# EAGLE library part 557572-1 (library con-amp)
AMP connector
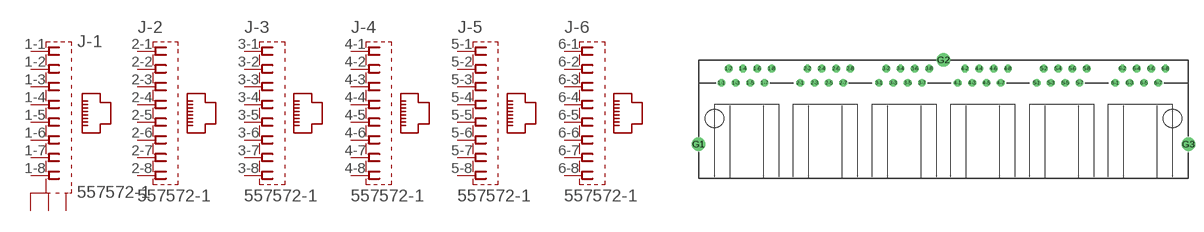
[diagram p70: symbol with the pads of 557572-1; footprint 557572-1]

Designator prefix J; gates -1=JACK8SH3 -2=JACK8_SH -3=JACK8_SH -4=JACK8_SH -5=JACK8_SH -6=JACK8_SH

## 557572-1 (MPN: 5557572-1; OC_FARNELL: unknown; OC_NEWARK: 14N8801)  [557572-1]
1-1  -1:1  pas
1-2  -1:2  pas
1-3  -1:3  pas
1-4  -1:4  pas
1-5  -1:5  pas
1-6  -1:6  pas
1-7  -1:7  pas
1-8  -1:8  pas
2-1  -2:1  pas
2-2  -2:2  pas
2-3  -2:3  pas
2-4  -2:4  pas
2-5  -2:5  pas
2-6  -2:6  pas
2-7  -2:7  pas
2-8  -2:8  pas
3-1  -3:1  pas
3-2  -3:2  pas
3-3  -3:3  pas
3-4  -3:4  pas
3-5  -3:5  pas
3-6  -3:6  pas
3-7  -3:7  pas
3-8  -3:8  pas
4-1  -4:1  pas
4-2  -4:2  pas
4-3  -4:3  pas
4-4  -4:4  pas
4-5  -4:5  pas
4-6  -4:6  pas
4-7  -4:7  pas
4-8  -4:8  pas
5-1  -5:1  pas
5-2  -5:2  pas
5-3  -5:3  pas
5-4  -5:4  pas
5-5  -5:5  pas
5-6  -5:6  pas
5-7  -5:7  pas
5-8  -5:8  pas
6-1  -6:1  pas
6-2  -6:2  pas
6-3  -6:3  pas
6-4  -6:4  pas
6-5  -6:5  pas
6-6  -6:6  pas
6-7  -6:7  pas
6-8  -6:8  pas
G1  -1:9  pas
G2  -1:10  pas
G3  -1:11  pas

## Footprint 557572-1 (pad centres in mm)
Modular Jack Shielded
drill 0.889 round: 1-1 -39.37,6.35; 1-2 -38.1,8.89; 1-3 -36.83,6.35; 1-4 -35.56,8.89; 1-5 -34.29,6.35; 1-6 -33.02,8.89; 1-7 -31.75,6.35; 1-8 -30.48,8.89; 2-1 -25.4,6.35; 2-2 -24.13,8.89; 2-3 -22.86,6.35; 2-4 -21.59,8.89; 2-5 -20.32,6.35; 2-6 -19.05,8.89; 2-7 -17.78,6.35; 2-8 -16.51,8.89; 3-1 -11.43,6.35; 3-2 -10.16,8.89; 3-3 -8.89,6.35; 3-4 -7.62,8.89; 3-5 -6.35,6.35; 3-6 -5.08,8.89; 3-7 -3.81,6.35; 3-8 -2.54,8.89; 4-1 2.54,6.35; 4-2 3.81,8.89; 4-3 5.08,6.35; 4-4 6.35,8.89; 4-5 7.62,6.35; 4-6 8.89,8.89; 4-7 10.16,6.35; 4-8 11.43,8.89; 5-1 16.51,6.35; 5-2 17.78,8.89; 5-3 19.05,6.35; 5-4 20.32,8.89; 5-5 21.59,6.35; 5-6 22.86,8.89; 5-7 24.13,6.35; 5-8 25.4,8.89; 6-1 30.48,6.35; 6-2 31.75,8.89; 6-3 33.02,6.35; 6-4 34.29,8.89; 6-5 35.56,6.35; 6-6 36.83,8.89; 6-7 38.1,6.35; 6-8 39.37,8.89
drill 1.575 pad 2.184 round: G1 -43.434,-4.572; G2 0,10.414; G3 43.434,-4.572
hole 3.251 at -40.64,0
hole 3.251 at 40.64,0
